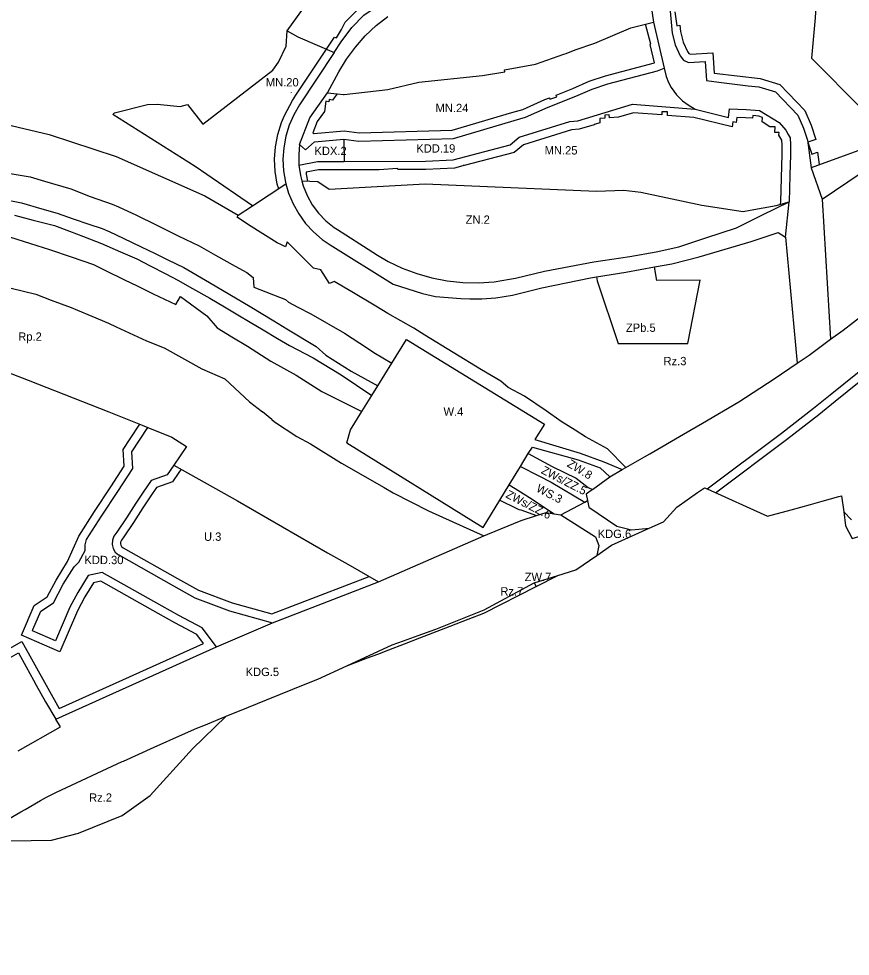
# Model space of a CAD drawing. Extents: x 7414808 to 7417449, y 5544732 to 5546764.
# Drawn here: x 7415397 to 7415896, y 5544811 to 5545373 of the extents above; entities that cross this region are included whole.
import ezdxf

# ---------------------------------------------------------------- set-up
doc = ezdxf.new("R2010")
doc.units = 0
for name, color, linetype in [('LIN_Linie Rozgraniczajace', 7, 'Continuous'), ('LIN_nieprzekraczale linie zabudowy', 7, 'Continuous'), ('TXT_Oznaczenia Przeznaczenia', 7, 'Continuous')]:
    doc.layers.add(name, color=color, linetype=linetype)

msp = doc.modelspace()

# ---------------------------------------------------------------- linework, layer by layer
at = {"layer": 'LIN_Linie Rozgraniczajace'}
for p, q in [((7415592.08, 5545300.72), (7415592.14, 5545287.42)), ((7415872.14, 5545283.71), (7415878.87, 5545264.85)), ((7415537.32, 5545260.8), (7415557.36, 5545273.95)), ((7415856.75, 5545242.09), (7415858.96, 5545263.19)), ((7415528.75, 5545255.18), (7415537.32, 5545260.8)), ((7415856.75, 5545242.09), (7415863.87, 5545166.56)), ((7415612.35, 5545153), (7415620.73, 5545166.52)), ((7415608.78, 5545147.23), (7415612.35, 5545153)), ((7415602.78, 5545137.54), (7415608.78, 5545147.23)), ((7415548.88, 5545132.75), (7415543.19, 5545137.41)), ((7415697.9, 5545104.66), (7415702.62, 5545112.34)), ((7415691.18, 5545093.71), (7415697.9, 5545104.66)), ((7415685.48, 5545084.43), (7415691.18, 5545093.71)), ((7415718.12, 5545076.25), (7415722.14, 5545075.55)), ((7415706.09, 5545034.83), (7415720.33, 5545039.33)), ((7415707.24, 5545032.63), (7415720.33, 5545039.33)), ((7415706.09, 5545034.83), (7415707.24, 5545032.63))]:
    msp.add_line(p, q, dxfattribs=at)
for points in [[(7415586.31, 5545352.83), (7415590.47, 5545359.11), (7415596.75, 5545367.73), (7415603.95, 5545375.04), (7415611.47, 5545380.19), (7415631.3, 5545395.08), (7415636.83, 5545399.56), (7415673.75, 5545427.08), (7415688.85, 5545437.37), (7415703.55, 5545449.17), (7415709.53, 5545454.48), (7415711.75, 5545456.75), (7415714.95, 5545460.36), (7415719.34, 5545466.14), (7415726.4, 5545476.38), (7415737.29, 5545492.46), (7415739.3, 5545495.31)], [(7415879.66, 5545460.27), (7415876.71, 5545449.65), (7415865.22, 5545424.25), (7415868.44, 5545414.11), (7415875.83, 5545393.73), (7415874.66, 5545373.55), (7415872.37, 5545349.31), (7415902.54, 5545318.9), (7415903.97, 5545317.38), (7415911.08, 5545297.88), (7415872.14, 5545283.71)], [(7415558.05, 5545365.8), (7415570.42, 5545382.89), (7415574.17, 5545384.63), (7415571.92, 5545400.24), (7415570.97, 5545406.83)], [(7415883.84, 5545180.87), (7415891.33, 5545186.37), (7415903.74, 5545195.97), (7416088.24, 5545343.29), (7416095.01, 5545348.55), (7416101.71, 5545353.47), (7416108.53, 5545358.23), (7416115.54, 5545362.83), (7416122.67, 5545367.28), (7416129.91, 5545371.52), (7416137.25, 5545375.58), (7416144.7, 5545379.44), (7416152.24, 5545383.12), (7416159.88, 5545386.6), (7416167.6, 5545389.88), (7416175.41, 5545392.96), (7416183.29, 5545395.84), (7416191.24, 5545398.51), (7416194.26, 5545399.44)], [(7415878.87, 5545264.85), (7415916.98, 5545290.63), (7415918.31, 5545291.75), (7415920.92, 5545314.03), (7415937.07, 5545383.68), (7415938.04, 5545387.87)], [(7415775.89, 5545383.12), (7415777.63, 5545370.86)], [(7415787.41, 5545379.82), (7415788.91, 5545364.43), (7415790.69, 5545357.27), (7415793.7, 5545350.68), (7415795.74, 5545348.17), (7415798.73, 5545346.68), (7415808.59, 5545347.3), (7415809.39, 5545335.93), (7415816.77, 5545334.97), (7415834.5, 5545332.86), (7415840.72, 5545332.14), (7415850.71, 5545329.11), (7415864.2, 5545315.19), (7415867.56, 5545307.45), (7415869.94, 5545300.14), (7415872.14, 5545283.71)], [(7415582.23, 5545328.58), (7415589.12, 5545341.21), (7415593.69, 5545348.78), (7415598.98, 5545355.99), (7415604.88, 5545362.7), (7415611.37, 5545368.86), (7415618.38, 5545374.41)], [(7415582.23, 5545328.58), (7415588, 5545328.02), (7415591.83, 5545327.65), (7415592.17, 5545327.51), (7415618.44, 5545330.65), (7415637.08, 5545334.99), (7415675.07, 5545338.93), (7415688.6, 5545341.26), (7415688.34, 5545342.35), (7415707.02, 5545345.76), (7415717.1, 5545349.42), (7415723.86, 5545351.69), (7415725.33, 5545352.12), (7415730.66, 5545354.4), (7415742.55, 5545358.4), (7415764.05, 5545367.49), (7415777.63, 5545370.86)], [(7415777.63, 5545370.86), (7415784.08, 5545343.46)], [(7415537.32, 5545260.8), (7415509.81, 5545279.65), (7415502.82, 5545284.4), (7415453.51, 5545315.63), (7415454.6, 5545316.55), (7415474.34, 5545321.57), (7415480.21, 5545321.8), (7415493.97, 5545320.47), (7415498.32, 5545321.62), (7415507.46, 5545309.82), (7415549.53, 5545342.19), (7415552.97, 5545346.96), (7415557.4, 5545356.61), (7415558.05, 5545365.8)], [(7415558.05, 5545365.8), (7415564.5, 5545362.2), (7415586.31, 5545352.83)], [(7415586.31, 5545352.83), (7415565.53, 5545321.46), (7415562.04, 5545315.48), (7415559.27, 5545309.13), (7415557.25, 5545302.51), (7415556, 5545295.69), (7415555.55, 5545288.78), (7415555.9, 5545281.87), (7415557.04, 5545275.04), (7415557.36, 5545273.95)], [(7415592.08, 5545300.72), (7415600.98, 5545299.57), (7415657.79, 5545301.29), (7415694.19, 5545311.97), (7415701.02, 5545313.97), (7415714.54, 5545319.95), (7415731.16, 5545326.62), (7415740.9, 5545330.87), (7415750.38, 5545334.05), (7415780.12, 5545341.83), (7415784.08, 5545343.46)], [(7415784.08, 5545343.46), (7415785.35, 5545338.3), (7415786.62, 5545334.85), (7415788.19, 5545331.77), (7415791.38, 5545327.31), (7415794.97, 5545323.8), (7415798.4, 5545321.35), (7415802.74, 5545318.83)], [(7415565.39, 5545297.65), (7415571.65, 5545313.69), (7415582.23, 5545328.58)], [(7415592.14, 5545287.42), (7415641.08, 5545287.63), (7415657.55, 5545288.37), (7415691.8, 5545297.38), (7415697.23, 5545301.93), (7415727.59, 5545311.41), (7415732.22, 5545311.73), (7415765.03, 5545321.7), (7415802.74, 5545318.83)], [(7415802.74, 5545318.83), (7415822.6, 5545313.88), (7415823.14, 5545318.9), (7415833.14, 5545318.69), (7415841.31, 5545318.03), (7415852.91, 5545310.75), (7415856.92, 5545306.25), (7415858.42, 5545303.57), (7415859.51, 5545301.64), (7415859.88, 5545297.44), (7415859.71, 5545291.45), (7415859.39, 5545279.29), (7415858.96, 5545263.19)], [(7415218.73, 5545302.75), (7415231.9, 5545305.73), (7415283.13, 5545313.83), (7415315.06, 5545314.38), (7415358.1, 5545313.84), (7415389.19, 5545309.83), (7415415.45, 5545303.53), (7415455.5, 5545290.5), (7415508.79, 5545266.77), (7415528.75, 5545255.18)], [(7415565.39, 5545297.65), (7415569.02, 5545294.5), (7415574.48, 5545299.15), (7415592.08, 5545300.72)], [(7415565.39, 5545297.65), (7415565.06, 5545291.53), (7415565.12, 5545285.21)], [(7415367.87, 5545284.27), (7415403.95, 5545278.26), (7415412.55, 5545275.65), (7415428.37, 5545270.96), (7415439.98, 5545266.49), (7415453.12, 5545261.94), (7415456.91, 5545260.27), (7415467.75, 5545255.18), (7415479.57, 5545249.44), (7415492.77, 5545242.96), (7415505.33, 5545236.86), (7415515.06, 5545231.33), (7415526.94, 5545224.66), (7415533.83, 5545220.83), (7415537.59, 5545217.86), (7415538.03, 5545212.07), (7415557, 5545204.7), (7415558.96, 5545203.13), (7415564.54, 5545200.19), (7415572.34, 5545196.07), (7415592.43, 5545184.48), (7415606.31, 5545175.6), (7415610.02, 5545172.89), (7415620.73, 5545166.52)], [(7415565.12, 5545285.21), (7415576.3, 5545287.35), (7415592.14, 5545287.42)], [(7415565.12, 5545285.21), (7415565.98, 5545278.95), (7415566.84, 5545275.76)], [(7415557.36, 5545273.95), (7415558.96, 5545268.38), (7415561.64, 5545262), (7415565.03, 5545255.96), (7415569.1, 5545250.35), (7415573.78, 5545245.25), (7415579.02, 5545240.73), (7415583.77, 5545237.43), (7415621.57, 5545213.83), (7415639.24, 5545208.35), (7415647.04, 5545206.6), (7415662.08, 5545205.29), (7415667.55, 5545205.13), (7415674.75, 5545205.15), (7415683.1, 5545205.71), (7415693.05, 5545207.23), (7415710.74, 5545211.66), (7415739.87, 5545217.79), (7415743.44, 5545218.34)], [(7415566.84, 5545275.76), (7415576.42, 5545275.34), (7415583.29, 5545270.92), (7415640.75, 5545274.03), (7415743.48, 5545269.72), (7415759.91, 5545270.31), (7415770.14, 5545269.04), (7415806.64, 5545261.32), (7415831.49, 5545257.48), (7415835.69, 5545258.18), (7415851.15, 5545261.07), (7415858.96, 5545263.19)], [(7415566.84, 5545275.76), (7415567.62, 5545272.84), (7415570.02, 5545267), (7415573.14, 5545261.5), (7415576.92, 5545256.43), (7415581.32, 5545251.89), (7415586.25, 5545247.94), (7415588.27, 5545246.59), (7415593.3, 5545243.41), (7415612.17, 5545231.23), (7415618.58, 5545227.57), (7415627.04, 5545223.53), (7415635.82, 5545220.23), (7415644.85, 5545217.68), (7415654.06, 5545215.92), (7415663.39, 5545214.94), (7415672.76, 5545214.76), (7415682.12, 5545215.38), (7415691.39, 5545216.8), (7415695.04, 5545217.58), (7415712.32, 5545221.6), (7415741.92, 5545227.36), (7415763.56, 5545230.52), (7415779.19, 5545233.22), (7415792.79, 5545236.33), (7415808.97, 5545241.59), (7415827.35, 5545247.76), (7415843.11, 5545255.42), (7415858.96, 5545263.19)], [(7415386.71, 5545265.04), (7415398.74, 5545262.56), (7415411.03, 5545259.06), (7415420.26, 5545256.43), (7415429.76, 5545253.13), (7415439.11, 5545249.93), (7415447.1, 5545247.19), (7415451.73, 5545245.27), (7415459.68, 5545241.49), (7415470.47, 5545236.34), (7415478.93, 5545232.2), (7415486.56, 5545228.49), (7415496.09, 5545223.95), (7415511.44, 5545214.96), (7415523.72, 5545207.73), (7415535.81, 5545200.48), (7415550.1, 5545191.91), (7415557.93, 5545187.11), (7415575.38, 5545176.57), (7415581.34, 5545171.27), (7415596.42, 5545161.73), (7415612.35, 5545153)], [(7415878.87, 5545264.85), (7415883.84, 5545180.87)], [(7415394.59, 5545255.24), (7415405.8, 5545252.34), (7415418.55, 5545249.06), (7415427.57, 5545245.57), (7415436.05, 5545242.39), (7415446.76, 5545238.28), (7415458.24, 5545233.32), (7415467.92, 5545229.14), (7415475.91, 5545224.89), (7415485.25, 5545220.03), (7415492.52, 5545216.32), (7415501.38, 5545211.26), (7415511.78, 5545205.41), (7415520.43, 5545200.25), (7415528.44, 5545195.5), (7415535.87, 5545191.12), (7415543.59, 5545186.49), (7415552.25, 5545181.3), (7415559.39, 5545177.06), (7415573.7, 5545169.8), (7415590.44, 5545159.55), (7415608.78, 5545147.23)], [(7415760.99, 5545103.98), (7415750.11, 5545115.12), (7415736.85, 5545122.39), (7415730.7, 5545126.44), (7415722.27, 5545131.66), (7415713.23, 5545138.04), (7415700.29, 5545146.7), (7415690.52, 5545151.93), (7415686.13, 5545155.81), (7415674.5, 5545162.51), (7415640.58, 5545183.37), (7415634.03, 5545187.54), (7415618.39, 5545196.36), (7415611.3, 5545200.74), (7415596.86, 5545209.29), (7415586.27, 5545215.49), (7415583.39, 5545214.37), (7415578.17, 5545222.41), (7415573.89, 5545223.43), (7415567.07, 5545230.36), (7415558.12, 5545239.34), (7415556.97, 5545236.28), (7415554.73, 5545237.49), (7415552.15, 5545238.65), (7415534.88, 5545249.48), (7415528.02, 5545254.09), (7415528.75, 5545255.18)], [(7415778.23, 5545224.23), (7415788.71, 5545226.17), (7415805.01, 5545230.32), (7415836.28, 5545239.48), (7415852.35, 5545244.89), (7415856.75, 5545242.09)], [(7415391.71, 5545242.23), (7415404.26, 5545238.29), (7415415.66, 5545234.75), (7415428.61, 5545230.36), (7415441.91, 5545225.74), (7415448.83, 5545222.29), (7415460.58, 5545216.55), (7415468.16, 5545212.86), (7415477.75, 5545208.04), (7415491.31, 5545201.77), (7415494.22, 5545206.54), (7415509.87, 5545194.89), (7415516.02, 5545187.75), (7415524.84, 5545182.39), (7415534.33, 5545176.67), (7415548.33, 5545167.84), (7415563.38, 5545159.34), (7415578.78, 5545149.48), (7415602.78, 5545137.54)], [(7415743.44, 5545218.34), (7415743.93, 5545215.82), (7415756.57, 5545178.27), (7415798.17, 5545178.25), (7415805.7, 5545216.22), (7415779.69, 5545216.05), (7415778.23, 5545224.23)], [(7415743.44, 5545218.34), (7415761.03, 5545221.05), (7415778.23, 5545224.23)], [(7415392.67, 5545211.59), (7415407.31, 5545207.92), (7415416.54, 5545204.4), (7415428.63, 5545199.92), (7415432.46, 5545198.23), (7415441.05, 5545194.69), (7415450.94, 5545190.62), (7415455.6, 5545188.26), (7415473.77, 5545179.91), (7415484.3, 5545175.7), (7415506.83, 5545163.19), (7415520.77, 5545157.16), (7415535.43, 5545143.44), (7415543.19, 5545137.41)], [(7415192.85, 5545143.26), (7415243.15, 5545171.84), (7415251.87, 5545181.6), (7415287.99, 5545201.37), (7415324.15, 5545186.94), (7415361.75, 5545172.1), (7415402.89, 5545156.35), (7415451.13, 5545137.38), (7415471.07, 5545129.37), (7415474.52, 5545127.99)], [(7415891.69, 5545077.35), (7415892.76, 5545069.1), (7415896.72, 5545061.5), (7415914.97, 5545066.87), (7415947.19, 5545076.34), (7415988.24, 5545087.59), (7416000.33, 5545090.81), (7416067.93, 5545108.9), (7416159.73, 5545133.73), (7416164.61, 5545134.98), (7416176.73, 5545137.86), (7416193.72, 5545141.89), (7416228.15, 5545148.01), (7416247.85, 5545151.24), (7416334.49, 5545162.77), (7416398.97, 5545171.36), (7416479.74, 5545182.19), (7416560.12, 5545193.01), (7416562.54, 5545193.44), (7416572.38, 5545195.24)], [(7415620.73, 5545166.52), (7415629.58, 5545180.81), (7415712.29, 5545129.96), (7415706.5, 5545120.74), (7415733.74, 5545112.55), (7415747.95, 5545107.48), (7415758.87, 5545102.76)], [(7415809.88, 5545091.14), (7415854.32, 5545124.5), (7415873.65, 5545139.57), (7415883.49, 5545147.52), (7415926.53, 5545182.17)], [(7415863.87, 5545166.56), (7415870.94, 5545171.4), (7415883.84, 5545180.87)], [(7415760.99, 5545103.98), (7415772.26, 5545110.47), (7415775.44, 5545112.3), (7415795.65, 5545123.93), (7415807.05, 5545130.49), (7415828.77, 5545143.45), (7415850.08, 5545157.09), (7415863.87, 5545166.56)], [(7415548.88, 5545132.75), (7415550.42, 5545131.43), (7415563.82, 5545122.6), (7415572.03, 5545118.1), (7415590.65, 5545106.56), (7415616.22, 5545092.04), (7415621.61, 5545088.91), (7415642.79, 5545078.01), (7415675.89, 5545063.04)], [(7415593.77, 5545118.72), (7415595.95, 5545126.51), (7415602.78, 5545137.54)], [(7415515.79, 5544996.52), (7415507.13, 5545007.92), (7415493.14, 5545015.26), (7415483.09, 5545020.93), (7415447.09, 5545041.16), (7415438.83, 5545039.23), (7415432.53, 5545029.08), (7415427.78, 5545020.23), (7415419.12, 5545000.16), (7415405.35, 5545006.1), (7415405.68, 5545006.86), (7415410.47, 5545017.97), (7415418.06, 5545022.94), (7415423.87, 5545034.09), (7415427.53, 5545039.99), (7415430.34, 5545044.5), (7415433.26, 5545047.2), (7415436.96, 5545054.19), (7415437.01, 5545057.65), (7415437.79, 5545060.81), (7415446.76, 5545074.9), (7415456.49, 5545089.7), (7415465.53, 5545103.42), (7415464.89, 5545113.36), (7415474.52, 5545127.99), (7415488.93, 5545122.2), (7415497.71, 5545116.5), (7415490.06, 5545105.39), (7415486.08, 5545099.62), (7415476.5, 5545096.3), (7415471.73, 5545089.25), (7415467.39, 5545082.61), (7415461.77, 5545073.89), (7415455.92, 5545065.24), (7415454.25, 5545062.77), (7415453.28, 5545060.45), (7415453.08, 5545057.93), (7415453.67, 5545055.48), (7415454.99, 5545053.33), (7415456.92, 5545051.71), (7415457.13, 5545051.58), (7415489.96, 5545033.13), (7415502.75, 5545025.91), (7415523.59, 5545018.18), (7415549.22, 5545010.98)], [(7415593.77, 5545118.72), (7415675.48, 5545068.14), (7415685.48, 5545084.43)], [(7415702.62, 5545112.34), (7415705.04, 5545116.28), (7415732.59, 5545108.64), (7415745.7, 5545103.75), (7415751.41, 5545098.48)], [(7415702.62, 5545112.34), (7415716.97, 5545104.67), (7415731.33, 5545097.63), (7415738.55, 5545092.08), (7415741.06, 5545090.86)], [(7415490.06, 5545105.39), (7415528.21, 5545083.99), (7415582.33, 5545052.93), (7415594.43, 5545045.99), (7415612.74, 5545035.49)], [(7415697.9, 5545104.66), (7415708.92, 5545099.02), (7415716.32, 5545095.14), (7415736.44, 5545083.3)], [(7415741.06, 5545090.86), (7415751.41, 5545098.48)], [(7415751.41, 5545098.48), (7415758.87, 5545102.76)], [(7415758.87, 5545102.76), (7415760.99, 5545103.98)], [(7415691.18, 5545093.71), (7415694.83, 5545091.38), (7415699.48, 5545088.51), (7415703.29, 5545086.08), (7415718.12, 5545076.25)], [(7415741.06, 5545090.86), (7415737.33, 5545088.11), (7415738.07, 5545084.19)], [(7415775.08, 5545067.69), (7415783.72, 5545071.5), (7415791.75, 5545080.18), (7415804, 5545088.94), (7415808.26, 5545091.87), (7415809.88, 5545091.14)], [(7415809.88, 5545091.14), (7415846.09, 5545074.84), (7415860.28, 5545078.73), (7415871.69, 5545081.86), (7415878.86, 5545083.82), (7415888.76, 5545086.54), (7415890.43, 5545087), (7415891.69, 5545077.35)], [(7415685.48, 5545084.43), (7415695.67, 5545079.4), (7415697.03, 5545078.92), (7415698.07, 5545078.54), (7415707.55, 5545075.16)], [(7415722.14, 5545075.55), (7415736.44, 5545083.3)], [(7415736.44, 5545083.3), (7415738.07, 5545084.19)], [(7415738.07, 5545084.19), (7415738.81, 5545080.26), (7415755.61, 5545068.91), (7415763.76, 5545066.92), (7415764.7, 5545066.69), (7415775.08, 5545067.69)], [(7415707.55, 5545075.16), (7415713.42, 5545077.07), (7415718.12, 5545076.25)], [(7415891.69, 5545077.35), (7415896.32, 5545072.72)], [(7415675.89, 5545063.04), (7415678.42, 5545064.14), (7415698.39, 5545072.18), (7415707.55, 5545075.16)], [(7415722.14, 5545075.55), (7415742.82, 5545062.46), (7415744.9, 5545057.2), (7415743.68, 5545051.28)], [(7415743.68, 5545051.28), (7415752.45, 5545057.54), (7415775.08, 5545067.69)], [(7415612.74, 5545035.49), (7415675.89, 5545063.04)], [(7415720.33, 5545039.33), (7415731.04, 5545042.71), (7415743.68, 5545051.28)], [(7415396.9, 5544934.26), (7415422.13, 5544948.54), (7415419.31, 5544953.25), (7415515.79, 5544996.52), (7415549.22, 5545010.98), (7415612.74, 5545035.49)], [(7415593.83, 5544985.11), (7415621.06, 5544997.65), (7415627.87, 5545000.1), (7415636.57, 5545003.22), (7415647.15, 5545007.02), (7415676.07, 5545018.6), (7415706.09, 5545034.83)], [(7415593.83, 5544985.11), (7415606.31, 5544989.9), (7415612.34, 5544992.21), (7415619.03, 5544994.78), (7415628.49, 5544998.4), (7415637.53, 5545001.87), (7415655.72, 5545008.86), (7415666.58, 5545013.01), (7415676.01, 5545016.64), (7415707.24, 5545032.63)], [(7415339.14, 5544960.11), (7415351.96, 5544967.37), (7415365.01, 5544974.74), (7415377.38, 5544981.74), (7415380.57, 5544983.54), (7415389.95, 5544988.84), (7415397.06, 5544992.86), (7415401.63, 5544984.52), (7415406.06, 5544976.46), (7415407.65, 5544973.56), (7415413.1, 5544963.62), (7415419.31, 5544953.25)], [(7415521.54, 5544954.89), (7415534.9, 5544960.33), (7415545.64, 5544964.69), (7415569.76, 5544974.46), (7415576.48, 5544977.19), (7415593.83, 5544985.11)], [(7415254.6, 5544811.06), (7415307.29, 5544834.58), (7415307.72, 5544835.91), (7415310.37, 5544835.96), (7415341.31, 5544849.77), (7415342.78, 5544850.78), (7415358.22, 5544861.35), (7415367.57, 5544867.18), (7415371.76, 5544869.79), (7415373.42, 5544870.83), (7415383.07, 5544877), (7415392.48, 5544880.16), (7415416.88, 5544880.57), (7415432.92, 5544884.91), (7415459.21, 5544895.37), (7415475.98, 5544907.34), (7415501.33, 5544935.46), (7415521.54, 5544954.89)], [(7415366.55, 5544878.69), (7415372.72, 5544882.43), (7415377, 5544885.02), (7415383.2, 5544888.77), (7415388.88, 5544892.06), (7415398.49, 5544897.62), (7415401.04, 5544899.1), (7415410.17, 5544904.39), (7415413.81, 5544906.5), (7415419.85, 5544909.32), (7415459.07, 5544927.72), (7415459.92, 5544928.09), (7415478.35, 5544936.32), (7415495.36, 5544943.9), (7415503.89, 5544947.71), (7415508.17, 5544949.45), (7415521.54, 5544954.89)]]:
    msp.add_lwpolyline(points, dxfattribs=at)
at = {"layer": 'LIN_nieprzekraczale linie zabudowy'}
msp.add_line((7415421.32, 5544959.63), (7415508, 5544998.51), dxfattribs=at)
for points in [[(7415552.98, 5545271.08), (7415552.16, 5545273.93), (7415550.92, 5545281.33), (7415550.54, 5545288.82), (7415551.03, 5545296.31), (7415552.38, 5545303.69), (7415554.58, 5545310.87), (7415556.37, 5545314.98), (7415561.21, 5545323.98), (7415563.31, 5545327.16), (7415586.36, 5545361.96), (7415587.69, 5545361.52), (7415590.64, 5545366.61), (7415592.93, 5545370.97), (7415600.73, 5545378.89)], [(7415790.43, 5545377.14), (7415791.67, 5545368.8), (7415793.48, 5545369.12), (7415793.85, 5545365.28), (7415795.43, 5545358.93), (7415797.98, 5545353.34), (7415798.94, 5545352.16), (7415799.76, 5545351.75), (7415813.23, 5545352.6), (7415814.09, 5545340.41), (7415841.7, 5545337.11), (7415853.48, 5545333.58), (7415868.43, 5545318), (7415872.24, 5545309.22), (7415875.03, 5545300.69), (7415870.17, 5545299.09), (7415872.55, 5545291.84), (7415875.94, 5545292.94), (7415876.91, 5545285.6)], [(7415588.12, 5545328.01), (7415586.24, 5545325.59), (7415585.31, 5545324.28), (7415583.23, 5545324.64), (7415582.99, 5545323.26), (7415581.28, 5545323.56), (7415580.35, 5545317.3), (7415576.08, 5545311.3), (7415573.45, 5545304.56), (7415574.11, 5545304.13), (7415592.18, 5545305.75), (7415601.23, 5545304.58), (7415657, 5545306.27), (7415692.78, 5545316.77), (7415699.3, 5545318.68), (7415712.6, 5545324.56), (7415715.25, 5545325.62), (7415715.55, 5545324.8), (7415719.71, 5545326.16), (7415719.32, 5545327.25), (7415729.23, 5545331.23), (7415739.1, 5545335.54), (7415748.95, 5545338.84), (7415778.23, 5545346.5), (7415775.6, 5545357.65), (7415776.08, 5545357.78), (7415772.78, 5545369.66)], [(7415560.48, 5545328.91), (7415560.52, 5545328.88)], [(7415853.79, 5545261.79), (7415853.97, 5545263.52), (7415854.71, 5545291.59), (7415854.87, 5545297.3), (7415854.62, 5545300.13), (7415852.88, 5545303.24), (7415852.95, 5545304.83), (7415850.35, 5545304.83), (7415850.53, 5545308.14), (7415847.41, 5545308.3), (7415842.74, 5545311.23), (7415843.09, 5545313.73), (7415840.73, 5545314.57), (7415837.21, 5545315.04), (7415836.95, 5545313.37), (7415832.89, 5545313.69), (7415827.62, 5545313.8), (7415827.3, 5545310.81), (7415825.19, 5545311.12), (7415824.75, 5545308.19), (7415801.94, 5545313.88), (7415786.01, 5545315.09), (7415786.1, 5545317.13), (7415782.66, 5545317.29), (7415782.58, 5545315.35), (7415765.59, 5545316.64), (7415756.73, 5545313.95), (7415751.28, 5545313.63), (7415751.18, 5545315.33), (7415748.45, 5545315.2), (7415748.53, 5545313.4), (7415745.49, 5545313.28), (7415745.58, 5545310.56), (7415742.32, 5545309.57), (7415742.05, 5545309.56), (7415742.05, 5545309.49), (7415733.13, 5545306.78), (7415728.52, 5545306.46), (7415699.68, 5545297.46), (7415694.16, 5545292.83), (7415664.22, 5545284.95), (7415663.5, 5545285), (7415663.47, 5545284.76), (7415658.31, 5545283.4), (7415641.2, 5545282.63), (7415624.33, 5545282.56), (7415624.29, 5545283.21), (7415613.22, 5545282.51), (7415576.78, 5545282.35), (7415569.5, 5545280.96), (7415569.44, 5545279.75), (7415570.28, 5545275.61)], [(7415929.65, 5545178.27), (7415886.63, 5545143.63), (7415876.76, 5545135.65), (7415857.36, 5545120.53), (7415814.77, 5545088.56)], [(7415197.89, 5545146.13), (7415216.39, 5545135.48), (7415234.16, 5545125.06), (7415309.66, 5545078.88), (7415341.54, 5545057.42), (7415354.01, 5545047.01), (7415358.31, 5545042.5), (7415369.14, 5545031.14), (7415373.63, 5545022.88), (7415383.09, 5545003.45), (7415384.48, 5544991.49), (7415399.01, 5544999.71), (7415421.32, 5544959.63)], [(7415508, 5544998.51), (7415503.82, 5545004), (7415490.75, 5545010.87), (7415480.64, 5545016.57), (7415446.34, 5545035.85), (7415441.98, 5545034.83), (7415436.86, 5545026.58), (7415432.29, 5545018.05), (7415421.73, 5544993.59), (7415398.78, 5545003.49), (7415406.47, 5545021.33), (7415414.23, 5545026.41), (7415419.52, 5545036.56), (7415426.45, 5545047.72), (7415433.13, 5545062.8), (7415442.56, 5545077.61), (7415452.32, 5545092.45), (7415460.43, 5545104.77), (7415459.8, 5545114.72), (7415464.03, 5545121.15), (7415469.79, 5545129.89)], [(7415494.43, 5545102.94), (7415493.17, 5545101.11), (7415489.26, 5545095.44), (7415479.71, 5545092.12), (7415475.89, 5545086.48), (7415471.58, 5545079.89), (7415465.94, 5545071.13), (7415460.06, 5545062.44), (7415458.67, 5545060.38), (7415458.2, 5545059.25), (7415458.12, 5545058.33), (7415458.34, 5545057.43), (7415458.83, 5545056.64), (7415459.8, 5545055.82), (7415492.41, 5545037.49), (7415504.86, 5545030.46), (7415525.14, 5545022.94), (7415548.97, 5545016.24), (7415607.15, 5545038.69)]]:
    msp.add_lwpolyline(points, dxfattribs=at)

# ---------------------------------------------------------------- texts
at = {"layer": 'TXT_Oznaczenia Przeznaczenia'}
for s, p in [('MN.20', (7415545.27, 5545332.41)), ('MN.24', (7415647.03, 5545317)), ('KDX.2', (7415574.42, 5545291.28)), ('KDD.19', (7415635.46, 5545292.75)), ('MN.25', (7415712.42, 5545291.62)), ('ZN.2', (7415665.05, 5545250.07)), ('ZPb.5', (7415761.14, 5545185.32)), ('Rp.2', (7415396.87, 5545179.98)), ('Rz.3', (7415783.66, 5545165.3)), ('W.4', (7415651.8, 5545134.99)), ('U.3', (7415508.21, 5545060.07)), ('KDG.6', (7415744.22, 5545061.76)), ('KDD.30', (7415436.51, 5545046.07)), ('ZW.7', (7415700.45, 5545035.91)), ('Rz.7', (7415685.87, 5545027.28)), ('KDG.5', (7415533.15, 5544979)), ('Rz.2', (7415439.3, 5544903.68))]:
    msp.add_text(s, height=5, dxfattribs=at).set_placement(p)
for s, rotation, p in [('ZWs/ZZ.5', 332.6741, (7415709.9, 5545100.78)), ('ZW.8', 328.8519, (7415725.42, 5545104.91)), ('WS.3', 332.2337, (7415706.91, 5545089.92)), ('ZWs/ZZ.6', 332.6741, (7415688.68, 5545086.28))]:
    msp.add_text(s, height=5, rotation=rotation, dxfattribs=at).set_placement(p)

doc.saveas('drawing.dxf')
